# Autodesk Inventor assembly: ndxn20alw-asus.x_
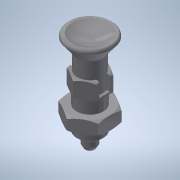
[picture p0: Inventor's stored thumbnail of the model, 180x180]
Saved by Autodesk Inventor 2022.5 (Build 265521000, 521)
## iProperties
Part Number: ndxn20alw-asus.x_
Material: 一般
Document SubType Name: Assembly
Designer: ImaoCorp
Sending System: SOLIDWORKS 2017-2017317
MC: AMD64
MC_MODEL: Intel64 Family 6 Model 60 Stepping 3, GenuineIntel
OS: Windows_NT
FRU: Parasolid Version 29.0, build 201,  4-17-2017
FORMAT: text
GUISE: transmit
KEY: ndxn20alw-asus
FILE: ndxn20alw-asus.x_t
DATE: Wed Sep 04 15:28:18 2019
Author: ImaoCorp
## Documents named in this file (3)
- X:\14_SW2022-Inv2022\00_全2023-1023新製品(TCC)まで\n\ndxn20alw-asus\NDXN20ALW-ASUS.iam
- X:\14_SW2022-Inv2022\00_全2023-1023新製品(TCC)まで\n\ndxn20alw-asus\ndxn20alw-asus_01.ipt
- X:\14_SW2022-Inv2022\00_全2023-1023新製品(TCC)まで\n\ndxn20alw-asus\ndxn20alw-asus_02.ipt
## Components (2 placed, 2 different names)
1. ndxn20alw-asus_01
2. ndxn20alw-asus_02
